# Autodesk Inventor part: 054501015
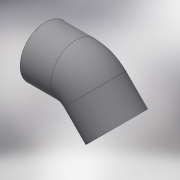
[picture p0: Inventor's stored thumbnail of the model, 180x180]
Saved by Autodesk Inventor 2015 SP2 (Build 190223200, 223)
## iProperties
Created: 2017-10
Part Number: 054501015
Material: Generic
Description: PLASSON THREADED 45° ELBOW HF 1.1/2"
Document SubType Name: Modeling
Designer: KIM
Mass: 83.8857 g
Surface Area: 243.302 cm^2
Volume: 83.8857 cm^3
Density: 1 g/cm^3
Appearance: Default
Author: KIM
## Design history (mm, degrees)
derived "054501.ipt"
feature "Solid1::054501.ipt"
tag "TaggingFeature1"
body "Solid1"
other parameters: "d7" = 0.44845, "d9" = 59, "d13" = 135 deg, "d18" = 12, "d19" = 45 deg, "d20" = 44.845, "d21" = 22, "d22" = 0, "d28" = 34, "d29" = 44.845, "d30" = 22, "d31" = 0, "d32" = 40.3605, "d33" = 45 deg, "E_" = 59, "lt_" = 22, "Z_" = 12, "G_" = 44.845
